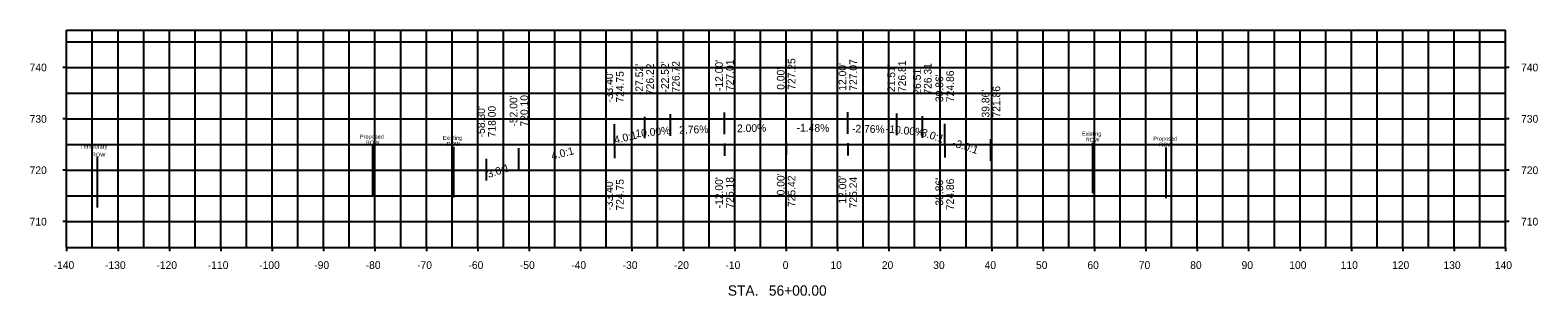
# Model space of a CAD drawing. Extents: x -147 to 146, y 696 to 747.
import ezdxf

# ---------------------------------------------------------------- set-up
doc = ezdxf.new("R2010")
doc.units = 0
for name, color, linetype in [('Default', 7, 'Continuous'), ('DisROW Existing', 7, 'Continuous'), ('DisROW Survey', 7, 'Continuous'), ('EXT_C', 7, 'Continuous'), ('phoSurveyPoints', 7, 'Continuous'), ('SurPointsNonDTM', 7, 'Continuous'), ('SurSurveyPoints', 7, 'Continuous')]:
    doc.layers.add(name, color=color, linetype=linetype)

msp = doc.modelspace()

# ---------------------------------------------------------------- linework, layer by layer
at = {"layer": 'DisROW Existing'}
msp.add_line((-134.03, 722.64), (-134.03, 712.73), dxfattribs=at)
at = {"layer": 'DisROW Survey'}
for p, q in [((-80.49, 724.8), (-80.49, 714.95)), ((59.63, 725.36), (59.63, 715.52)), ((59.63, 725.36), (59.63, 715.52)), ((59.63, 725.36), (59.63, 715.52)), ((59.63, 725.36), (59.63, 715.52)), ((59.63, 725.36), (59.63, 715.52)), ((-64.75, 724.55), (-64.75, 714.71)), ((-64.75, 724.55), (-64.75, 714.71)), ((-64.75, 724.55), (-64.75, 714.71)), ((-64.75, 724.55), (-64.75, 714.71)), ((73.89, 724.41), (73.89, 714.56))]:
    msp.add_line(p, q, dxfattribs=at)
at = {"layer": 'EXT_C'}
for p, q in [((-135, 705), (-135, 747.25)), ((-125, 705), (-125, 747.25)), ((-115, 705), (-115, 747.25)), ((-105, 705), (-105, 747.25)), ((-95, 705), (-95, 747.25)), ((-85, 705), (-85, 747.25)), ((-75, 705), (-75, 747.25)), ((-65, 705), (-65, 747.25)), ((-55, 705), (-55, 747.25)), ((-45, 705), (-45, 747.25)), ((-35, 705), (-35, 747.25)), ((-25, 705), (-25, 747.25)), ((-15, 705), (-15, 747.25)), ((-5, 705), (-5, 747.25)), ((5, 705), (5, 747.25)), ((15, 705), (15, 747.25)), ((25, 705), (25, 747.25)), ((35, 705), (35, 747.25)), ((45, 705), (45, 747.25)), ((55, 705), (55, 747.25)), ((65, 705), (65, 747.25)), ((75, 705), (75, 747.25)), ((85, 705), (85, 747.25)), ((95, 705), (95, 747.25)), ((105, 705), (105, 747.25)), ((115, 705), (115, 747.25)), ((125, 705), (125, 747.25)), ((135, 705), (135, 747.25)), ((-140, 745), (140, 745)), ((-140, 735), (140, 735)), ((-140, 725), (140, 725)), ((-140, 715), (140, 715))]:
    msp.add_line(p, q, dxfattribs=at)
at = {"layer": 'phoSurveyPoints'}
for p, q in [((-130, 705), (-130, 747.25)), ((-120, 705), (-120, 747.25)), ((-110, 705), (-110, 747.25)), ((-100, 705), (-100, 747.25)), ((-90, 705), (-90, 747.25)), ((-80, 705), (-80, 747.25)), ((-70, 705), (-70, 747.25)), ((-60, 705), (-60, 747.25)), ((-50, 705), (-50, 747.25)), ((-40, 705), (-40, 747.25)), ((-30, 705), (-30, 747.25)), ((-20, 705), (-20, 747.25)), ((-10, 705), (-10, 747.25)), ((0, 705), (0, 747.25)), ((10, 705), (10, 747.25)), ((20, 705), (20, 747.25)), ((30, 705), (30, 747.25)), ((40, 705), (40, 747.25)), ((50, 705), (50, 747.25)), ((60, 705), (60, 747.25)), ((70, 705), (70, 747.25)), ((80, 705), (80, 747.25)), ((90, 705), (90, 747.25)), ((100, 705), (100, 747.25)), ((110, 705), (110, 747.25)), ((120, 705), (120, 747.25)), ((130, 705), (130, 747.25)), ((-140, 740), (-140.72, 740)), ((-140, 740), (140, 740)), ((140.72, 740), (140, 740)), ((-140, 730), (-140.72, 730)), ((-140, 730), (140, 730)), ((140.72, 730), (140, 730)), ((-140, 720), (-140.72, 720)), ((-140, 720), (140, 720)), ((140.72, 720), (140, 720)), ((-140, 710), (-140.72, 710)), ((-140, 710), (140, 710)), ((140.72, 710), (140, 710)), ((-140, 705), (-140, 704.28)), ((-130, 705), (-130, 704.28)), ((-120, 705), (-120, 704.28)), ((-110, 705), (-110, 704.28)), ((-100, 705), (-100, 704.28)), ((-90, 705), (-90, 704.28)), ((-80, 705), (-80, 704.28)), ((-70, 705), (-70, 704.28)), ((-60, 705), (-60, 704.28)), ((-50, 705), (-50, 704.28)), ((-40, 705), (-40, 704.28)), ((-30, 705), (-30, 704.28)), ((-20, 705), (-20, 704.28)), ((-10, 705), (-10, 704.28)), ((0, 705), (0, 704.28)), ((10, 705), (10, 704.28)), ((20, 705), (20, 704.28)), ((30, 705), (30, 704.28)), ((40, 705), (40, 704.28)), ((50, 705), (50, 704.28)), ((60, 705), (60, 704.28)), ((70, 705), (70, 704.28)), ((80, 705), (80, 704.28)), ((90, 705), (90, 704.28)), ((100, 705), (100, 704.28)), ((110, 705), (110, 704.28)), ((120, 705), (120, 704.28)), ((130, 705), (130, 704.28)), ((140, 705), (140, 704.28))]:
    msp.add_line(p, q, dxfattribs=at)
at = {"layer": 'SurPointsNonDTM'}
for p, q in [((-140, 747.25), (140, 747.25)), ((-140, 705), (-140, 747.25)), ((140, 705), (140, 747.25)), ((-140, 705), (140, 705))]:
    msp.add_line(p, q, dxfattribs=at)
at = {"layer": 'SurSurveyPoints'}
for p, q in [((-22.52, 726.72), (-22.52, 730.92)), ((-12, 727.01), (-12, 731.21)), ((0, 727.25), (0, 731.45)), ((0, 727.25), (0, 731.45)), ((0, 727.25), (0, 731.45)), ((0, 727.25), (0, 731.45)), ((12, 727.07), (12, 731.27)), ((21.51, 726.81), (21.51, 731.01)), ((26.51, 726.31), (26.51, 730.51)), ((-33.4, 724.75), (-33.4, 728.95)), ((-27.52, 726.22), (-27.52, 730.42)), ((30.86, 724.86), (30.86, 729.06)), ((30.86, 724.86), (30.86, 729.06)), ((-33.4, 724.75), (-33.4, 722.35)), ((-12, 725.18), (-12, 722.78)), ((0, 725.42), (0, 723.02)), ((0, 725.42), (0, 723.02)), ((0, 725.42), (0, 723.02)), ((12, 725.24), (12, 722.84)), ((30.86, 724.86), (30.86, 722.46)), ((39.86, 721.86), (39.86, 726.06)), ((-58.3, 718), (-58.3, 722.2)), ((-52, 720.1), (-52, 724.3))]:
    msp.add_line(p, q, dxfattribs=at)

# ---------------------------------------------------------------- texts
at = {"layer": 'Default'}
for s, height, p in [('740', 1.5, (-147.2, 739.25)), ('740', 1.5, (143, 739.25)), ('730', 1.5, (-147.2, 729.25)), ('730', 1.5, (143, 729.25)), ('720', 1.5, (-147.2, 719.25)), ('720', 1.5, (143, 719.25)), ('710', 1.5, (-147.2, 709.25)), ('710', 1.5, (143, 709.25)), ('-140', 1.5, (-142.53, 700.8)), ('-130', 1.5, (-132.53, 700.8)), ('-120', 1.5, (-122.53, 700.8)), ('-110', 1.5, (-112.53, 700.8)), ('-100', 1.5, (-102.53, 700.8)), ('-90', 1.5, (-91.81, 700.8)), ('-80', 1.5, (-81.81, 700.8)), ('-70', 1.5, (-71.81, 700.8)), ('-60', 1.5, (-61.81, 700.8)), ('-50', 1.5, (-51.81, 700.8)), ('-40', 1.5, (-41.81, 700.8)), ('-30', 1.5, (-31.81, 700.8)), ('-20', 1.5, (-21.81, 700.8)), ('-10', 1.5, (-11.81, 700.8)), ('0', 1.5, (-0.67, 700.8)), ('10', 1.5, (8.62, 700.8)), ('20', 1.5, (18.62, 700.8)), ('30', 1.5, (28.62, 700.8)), ('40', 1.5, (38.62, 700.8)), ('50', 1.5, (48.62, 700.8)), ('60', 1.5, (58.62, 700.8)), ('70', 1.5, (68.62, 700.8)), ('80', 1.5, (78.62, 700.8)), ('90', 1.5, (88.62, 700.8)), ('100', 1.5, (97.9, 700.8)), ('110', 1.5, (107.9, 700.8)), ('120', 1.5, (117.9, 700.8)), ('130', 1.5, (127.9, 700.8)), ('140', 1.5, (137.9, 700.8)), ('STA.', 2.004, (-11.34, 695.6)), ('56+00.00', 2.004, (-3.36, 695.6))]:
    msp.add_text(s, height=height, dxfattribs=at).set_placement(p)
at = {"layer": 'DisROW Existing'}
for s, p in [('Temporary', (-137.36, 724.22)), ('ROW', (-135.11, 722.64))]:
    msp.add_text(s, height=0.793, dxfattribs=at).set_placement(p)
at = {"layer": 'DisROW Survey'}
for s, p in [('Existing', (57.54, 726.72)), ('Existing', (57.54, 726.72)), ('Existing', (57.54, 726.72)), ('Existing', (57.54, 726.72)), ('Existing', (57.54, 726.72)), ('Proposed', (-82.94, 726.15)), ('ROW', (-81.8, 724.97)), ('Existing', (-66.84, 725.9)), ('Existing', (-66.84, 725.9)), ('Existing', (-66.84, 725.9)), ('Existing', (-66.84, 725.9)), ('ROW', (-66.07, 724.72)), ('ROW', (-66.07, 724.72)), ('ROW', (-66.07, 724.72)), ('ROW', (-66.07, 724.72)), ('ROW', (58.31, 725.53)), ('ROW', (58.31, 725.53)), ('ROW', (58.31, 725.53)), ('ROW', (58.31, 725.53)), ('ROW', (58.31, 725.53)), ('Proposed', (71.43, 725.76)), ('ROW', (72.57, 724.58))]:
    msp.add_text(s, height=0.787, dxfattribs=at).set_placement(p)
at = {"layer": 'SurSurveyPoints'}
for s, rotation, p in [("-27.52'", 90, (-27.82, 734.62)), ('726.22', 90, (-25.72, 734.62)), ("-22.52'", 90, (-22.82, 735.12)), ('726.72', 90, (-20.72, 735.12)), ("-12.00'", 90, (-12.3, 735.41)), ('727.01', 90, (-10.2, 735.41)), ("0.00'", 90, (-0.3, 735.65)), ("0.00'", 90, (-0.3, 735.65)), ("0.00'", 90, (-0.3, 735.65)), ("0.00'", 90, (-0.3, 735.65)), ('727.25', 90, (1.8, 735.65)), ('727.25', 90, (1.8, 735.65)), ('727.25', 90, (1.8, 735.65)), ('727.25', 90, (1.8, 735.65)), ("12.00'", 90, (11.7, 735.47)), ('727.07', 90, (13.8, 735.47)), ("21.51'", 90, (21.21, 735.21)), ('726.81', 90, (23.31, 735.21)), ("26.51'", 90, (26.21, 734.71)), ('726.31', 90, (28.31, 734.71)), ('724.86', 90, (32.66, 733.26)), ('724.86', 90, (32.66, 733.26)), ("-33.40'", 90, (-33.7, 733.15)), ('724.75', 90, (-31.6, 733.15)), ("30.86'", 90, (30.56, 733.26)), ("30.86'", 90, (30.56, 733.26)), ("-52.00'", 90, (-52.3, 728.5)), ('720.10', 90, (-50.2, 728.5)), ("39.86'", 90, (39.56, 730.26)), ('721.86', 90, (41.66, 730.26)), ("-58.30'", 90, (-58.6, 726.4)), ('718.00', 90, (-56.5, 726.4)), ('4.0:1', 14.0362, (-33.26, 725.12)), ('10.00%', 5.7106, (-29.25, 726.38)), ('2.76%', 1.5788, (-20.79, 727.1)), ('2.00%', 1.1458, (-9.54, 727.39)), ('-1.48%', 359.1541, (2.04, 727.55)), ('-2.76%', 358.4212, (12.79, 727.38)), ('-10.00%', 354.2894, (19.36, 727.36)), ('-3.0:1', 341.5668, (25.55, 726.96)), ('-3.0:1', 341.5668, (32.23, 724.74)), ('4.0:1', 14.0362, (-45.5, 722.06)), ('3.0:1', 18.4332, (-57.89, 718.47)), ("0.00'", 90, (-0.3, 715.11)), ("0.00'", 90, (-0.3, 715.11)), ("0.00'", 90, (-0.3, 715.11)), ('725.42', 90, (1.8, 712.85)), ('725.42', 90, (1.8, 712.85)), ('725.42', 90, (1.8, 712.85)), ("12.00'", 90, (11.7, 713.5)), ("-33.40'", 90, (-33.7, 712.15)), ('724.75', 90, (-31.6, 712.15)), ("-12.00'", 90, (-12.3, 712.58)), ('725.18', 90, (-10.2, 712.56)), ('725.24', 90, (13.8, 712.59)), ("30.86'", 90, (30.56, 713.12)), ('724.86', 90, (32.66, 712.23))]:
    msp.add_text(s, height=1.5, rotation=rotation, dxfattribs=at).set_placement(p)

doc.saveas('drawing.dxf')
